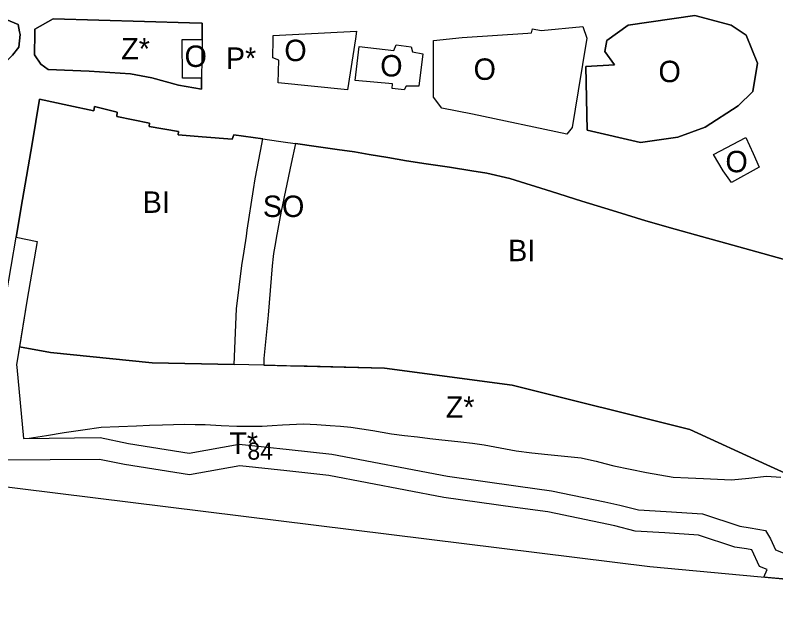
# Model space of a CAD drawing. Extents: x -521621 to -516769, y -1190068 to -1185078.
# Drawn here: x -519302 to -518947.5, y -1187581.5 to -1187307.9 of the extents above; entities that cross this region are included whole.
import ezdxf

# ---------------------------------------------------------------- set-up
doc = ezdxf.new("R2010")
doc.units = 0
for name, color, linetype in [('bydleni_s', 7, 'Continuous'), ('fpl_id', 7, 'Continuous'), ('s_zelen_s', 7, 'Continuous'), ('sm_vyuziti_s', 7, 'Continuous'), ('v_infrastr_n', 7, 'Continuous'), ('v_infrastr_s', 7, 'Continuous')]:
    doc.layers.add(name, color=color, linetype=linetype)

msp = doc.modelspace()

# ---------------------------------------------------------------- linework, layer by layer
at = {"layer": 'bydleni_s'}
for p, q in [((-519214.96, -1187364.54), (-519226.07, -1187363.63)), ((-519200.88, -1187365.69), (-519214.96, -1187364.54)), ((-519152.01, -1187370.5), (-519161.84, -1187369.1)), ((-519128.44, -1187374.31), (-519137.12, -1187372.82)), ((-519119.6, -1187375.83), (-519128.44, -1187374.31)), ((-519110.5, -1187377.14), (-519119.6, -1187375.83)), ((-519099.69, -1187378.8), (-519110.5, -1187377.14)), ((-519089.19, -1187380.42), (-519099.69, -1187378.8)), ((-519082.28, -1187381.48), (-519089.19, -1187380.42)), ((-519071.47, -1187384.11), (-519082.28, -1187381.48)), ((-519052.05, -1187390.16), (-519071.47, -1187384.11)), ((-519037.91, -1187394.56), (-519052.05, -1187390.16)), ((-519023.63, -1187399.01), (-519037.91, -1187394.56)), ((-519017.05, -1187401.06), (-519023.63, -1187399.01)), ((-519008.05, -1187403.86), (-519017.05, -1187401.06)), ((-518994.45, -1187407.64), (-519008.05, -1187403.86)), ((-518982.16, -1187411.05), (-518994.45, -1187407.64)), ((-518970.39, -1187414.32), (-518982.16, -1187411.05)), ((-518959.17, -1187417.44), (-518970.39, -1187414.32)), ((-518944.16, -1187421.61), (-518959.17, -1187417.44))]:
    msp.add_line(p, q, dxfattribs=at)
for points in [[(-519277.04, -1187349.99), (-519290.68, -1187347.06), (-519294.21, -1187367.8), (-519298.64, -1187393.79)], [(-519265.4, -1187352.49), (-519277.04, -1187349.99)], [(-519254.63, -1187355.11), (-519254.54, -1187353.15), (-519265.03, -1187350.52), (-519265.4, -1187352.49)], [(-519239.65, -1187359.79), (-519239.46, -1187358.2), (-519254.63, -1187355.11)], [(-519226.07, -1187363.63), (-519225.88, -1187362.13), (-519239.65, -1187359.79)], [(-519196.44, -1187424.58), (-519195.4, -1187417.92), (-519194.31, -1187410.93), (-519193.87, -1187408.08), (-519190.92, -1187389.18), (-519190.15, -1187384.26), (-519187.66, -1187371.24), (-519186.58, -1187365.58), (-519200.13, -1187363.65), (-519200.88, -1187365.69)], [(-519161.84, -1187369.1), (-519171.37, -1187367.75), (-519173.38, -1187377.11), (-519178.15, -1187399.27), (-519180.35, -1187411.82), (-519180.72, -1187413.92), (-519181.61, -1187418.96), (-519181.86, -1187420.41), (-519182.22, -1187424.83)], [(-519137.12, -1187372.82), (-519143.9, -1187371.66), (-519152.01, -1187370.5)], [(-519298.64, -1187393.79), (-519301.65, -1187411.41), (-519291.84, -1187413.36)], [(-519291.84, -1187413.36), (-519296.46, -1187440.4), (-519300.11, -1187462.57), (-519285.55, -1187465.16), (-519238.18, -1187469.96), (-519199.96, -1187470.86), (-519198.95, -1187444.91)], [(-519198.95, -1187444.91), (-519196.44, -1187424.58)], [(-519182.22, -1187424.83), (-519184.17, -1187447.8), (-519186.1, -1187468.02), (-519186.18, -1187471.19), (-519129.96, -1187472.52), (-519070.49, -1187480.41), (-518987.59, -1187501.17), (-518951.77, -1187517.59)], [(-518951.77, -1187517.59), (-518938.37, -1187523.73), (-518937.12, -1187522.83)]]:
    msp.add_lwpolyline(points, dxfattribs=at)
at = {"layer": 's_zelen_s'}
for points in [[(-519340.83, -1187326.07), (-519308.14, -1187331.14), (-519303.3, -1187326.48), (-519300.34, -1187322.71), (-519299.8, -1187316.88), (-519300.01, -1187315.67), (-519300.61, -1187312.13), (-519306.33, -1187309.9), (-519322.8, -1187308.87), (-519367.14, -1187306.08), (-519395.14, -1187302.99), (-519449.32, -1187297), (-519480.57, -1187293.55), (-519511.5, -1187291.57), (-519525.87, -1187288.75), (-519526.08, -1187289.83), (-519527.1, -1187295.05), (-519498.34, -1187299.98), (-519398.99, -1187315.96), (-519340.83, -1187326.07)], [(-519224.22, -1187319.17), (-519214.96, -1187319.25), (-519214.91, -1187311.57), (-519220.85, -1187311.4), (-519241.74, -1187310.81), (-519284.42, -1187309.62), (-519292.9, -1187314.37), (-519292.91, -1187316.03), (-519292.99, -1187326.39), (-519290.12, -1187330.7), (-519286.71, -1187333.21), (-519267.61, -1187334.02), (-519248.26, -1187335.27), (-519238.31, -1187337.06), (-519225.93, -1187340.47), (-519215.19, -1187342.31), (-519215.19, -1187337.23), (-519224.06, -1187337.31), (-519224.22, -1187319.17)], [(-519300.11, -1187462.57), (-519301.49, -1187470.89), (-519301.23, -1187472.1), (-519298.18, -1187505.33), (-519295.55, -1187505.13)], [(-519199.96, -1187470.86), (-519238.18, -1187469.96), (-519285.55, -1187465.16), (-519300.11, -1187462.57)], [(-519186.18, -1187471.19), (-519193.2, -1187471.02), (-519199.96, -1187470.86)], [(-519175.55, -1187471.44), (-519186.18, -1187471.19)], [(-519166.03, -1187471.66), (-519175.55, -1187471.44)], [(-518951.77, -1187517.59), (-518987.59, -1187501.17), (-519070.49, -1187480.41), (-519129.96, -1187472.52), (-519166.03, -1187471.66)], [(-519295.55, -1187505.13), (-519287.41, -1187503.86), (-519279.26, -1187502.6), (-519270.6, -1187501.33), (-519261.94, -1187500.07), (-519253.7, -1187499.74), (-519245.46, -1187499.41), (-519239.43, -1187499.15), (-519233.4, -1187498.89), (-519228.23, -1187498.74), (-519223.06, -1187498.58), (-519218.24, -1187498.72), (-519213.43, -1187498.85), (-519206.12, -1187499.23), (-519198.82, -1187499.6), (-519192.88, -1187499.55), (-519186.93, -1187499.51), (-519182.2, -1187499.2), (-519177.46, -1187498.89)], [(-519177.46, -1187498.89), (-519167.66, -1187498.42)], [(-519167.66, -1187498.42), (-519161.42, -1187498.86), (-519155.19, -1187499.3), (-519150.43, -1187499.64), (-519145.67, -1187499.97), (-519140.5, -1187500.81), (-519135.33, -1187501.66), (-519131.01, -1187502.4), (-519126.68, -1187503.13), (-519120.62, -1187503.86), (-519114.57, -1187504.6), (-519108.86, -1187505.29), (-519103.15, -1187505.98), (-519098.75, -1187506.41), (-519094.35, -1187506.83), (-519088.91, -1187507.56), (-519083.47, -1187508.3), (-519076.03, -1187509.73), (-519068.58, -1187511.15), (-519061.21, -1187512), (-519053.84, -1187512.85), (-519046.09, -1187513.58), (-519038.33, -1187514.32), (-519034.82, -1187515.09), (-519031.31, -1187515.86), (-519027.18, -1187516.98), (-519023.06, -1187518.1), (-519015.46, -1187519.68), (-519007.85, -1187521.26), (-519001.6, -1187522.34), (-518995.35, -1187523.42), (-518988.33, -1187523.69), (-518981.31, -1187523.96), (-518974.75, -1187524.31), (-518968.19, -1187524.66), (-518960.05, -1187523.81), (-518951.91, -1187522.96), (-518945.14, -1187523.34)], [(-518938.37, -1187523.73), (-518951.77, -1187517.59)]]:
    msp.add_lwpolyline(points, dxfattribs=at)
at = {"layer": 'sm_vyuziti_s'}
for points in [[(-519196.44, -1187424.58), (-519195.4, -1187417.92), (-519194.31, -1187410.93), (-519193.87, -1187408.08), (-519190.92, -1187389.18), (-519190.15, -1187384.26), (-519187.66, -1187371.24), (-519186.58, -1187365.58), (-519179.4, -1187366.6), (-519174.98, -1187367.23), (-519171.37, -1187367.75), (-519173.38, -1187377.11), (-519178.15, -1187399.27), (-519180.35, -1187411.82), (-519180.72, -1187413.92), (-519181.61, -1187418.96), (-519181.86, -1187420.41), (-519182.22, -1187424.83)], [(-519186.18, -1187471.19), (-519193.2, -1187471.02), (-519199.96, -1187470.86), (-519198.95, -1187444.91), (-519196.44, -1187424.58)], [(-519182.22, -1187424.83), (-519184.17, -1187447.8), (-519186.1, -1187468.02), (-519186.18, -1187471.19)]]:
    msp.add_lwpolyline(points, dxfattribs=at)
at = {"layer": 'v_infrastr_n'}
for points in [[(-519306.32, -1187438.74), (-519301.65, -1187411.41), (-519291.84, -1187413.36), (-519296.46, -1187440.4), (-519301.49, -1187470.89), (-519301.23, -1187472.1), (-519298.18, -1187505.33), (-519262.49, -1187504.9), (-519249.3, -1187507.6), (-519220.9, -1187512.16), (-519197.67, -1187507.99), (-519174.37, -1187510.46), (-519154.46, -1187512.62), (-519100.6, -1187522.96), (-519067.64, -1187527.61), (-519052.16, -1187529.73), (-519027.25, -1187534.85), (-519020.25, -1187536.36), (-519011.55, -1187538.56), (-518998.58, -1187539.34), (-518981.68, -1187540.49), (-518964.24, -1187546.2), (-518959.53, -1187546.94), (-518952.28, -1187548.29), (-518950.02, -1187552.18), (-518947.74, -1187557.27), (-518938.14, -1187561)], [(-519790.94, -1187475.66), (-519421.47, -1187513.5), (-519006.29, -1187565.08), (-518941.03, -1187571.03), (-518921.54, -1187583.59)], [(-518941.03, -1187571.03), (-518953.05, -1187569.94), (-518951.61, -1187566.49), (-518955.19, -1187565.1), (-518958.7, -1187557.27), (-518961.22, -1187556.8), (-518966.59, -1187555.95), (-518983.6, -1187550.38), (-518999.22, -1187549.32), (-519013.09, -1187548.49), (-519022.53, -1187546.1), (-519029.31, -1187544.64), (-519053.85, -1187539.59), (-519069.02, -1187537.51), (-519102.24, -1187532.83), (-519155.94, -1187522.52), (-519175.44, -1187520.4), (-519197.31, -1187518.08), (-519220.81, -1187522.3), (-519251.1, -1187517.44), (-519262.71, -1187515.06), (-519308.73, -1187515.41)]]:
    msp.add_lwpolyline(points, dxfattribs=at)
at = {"layer": 'v_infrastr_s'}
msp.add_line((-519119.6, -1187375.83), (-519110.5, -1187377.14), dxfattribs=at)
for points in [[(-519340.83, -1187326.07), (-519398.99, -1187315.96), (-519498.34, -1187299.98), (-519527.1, -1187295.05), (-519526.08, -1187289.83), (-519525.87, -1187288.75), (-519511.5, -1187291.57), (-519480.57, -1187293.55), (-519449.32, -1187297), (-519395.14, -1187302.99), (-519367.14, -1187306.08), (-519322.8, -1187308.87), (-519306.33, -1187309.9), (-519300.61, -1187312.13), (-519300.01, -1187315.67), (-519299.8, -1187316.88), (-519300.34, -1187322.71), (-519303.3, -1187326.48), (-519308.14, -1187331.14), (-519340.83, -1187326.07)], [(-519215.19, -1187337.23), (-519215.19, -1187342.31), (-519225.93, -1187340.47), (-519238.31, -1187337.06), (-519248.26, -1187335.27), (-519267.61, -1187334.02), (-519286.71, -1187333.21), (-519290.12, -1187330.7), (-519292.99, -1187326.39), (-519292.91, -1187316.03), (-519292.9, -1187314.37), (-519284.42, -1187309.62), (-519241.74, -1187310.81), (-519220.85, -1187311.4), (-519214.91, -1187311.57), (-519214.96, -1187319.25)], [(-518958.2, -1187343.4), (-518956, -1187330.25), (-518961.33, -1187317.13), (-518968.31, -1187312.54), (-518985.28, -1187308.06), (-519016.3, -1187312.54), (-519026.33, -1187319.64), (-519027.26, -1187324.73), (-519022.79, -1187331.06), (-519036.06, -1187331.83), (-519035.44, -1187361.46), (-519010.67, -1187367.17), (-518993.16, -1187364.78), (-518980.5, -1187360.15), (-518965.07, -1187350.12), (-518958.2, -1187343.4)], [(-519010.67, -1187367.17), (-519035.44, -1187361.46), (-519036.06, -1187331.83), (-519022.79, -1187331.06), (-519027.26, -1187324.73), (-519026.33, -1187319.64), (-519016.3, -1187312.54), (-518985.28, -1187308.06), (-518968.31, -1187312.54), (-518961.33, -1187317.13), (-518956, -1187330.25), (-518958.2, -1187343.4)], [(-519107.09, -1187319.64), (-519093.74, -1187318.21), (-519063.09, -1187316.17), (-519061.33, -1187316.05), (-519060.94, -1187314.2), (-519056.93, -1187315.05), (-519037.41, -1187313.19), (-519035.63, -1187318.52), (-519039.68, -1187343.1), (-519042.5, -1187360.19), (-519045.01, -1187363.39)], [(-519056.93, -1187315.05), (-519037.41, -1187313.19), (-519035.63, -1187318.52), (-519039.68, -1187343.1)], [(-519181.85, -1187319.02), (-519181.82, -1187317.28), (-519142.93, -1187315.35), (-519143.47, -1187318.86)], [(-519093.74, -1187318.21), (-519063.09, -1187316.17), (-519061.33, -1187316.05), (-519060.94, -1187314.2), (-519056.93, -1187315.05)], [(-519214.96, -1187319.25), (-519215.19, -1187337.23)], [(-519143.47, -1187318.86), (-519147.15, -1187342.73), (-519179.48, -1187339.49), (-519179.19, -1187328.78), (-519181.97, -1187327.7), (-519181.85, -1187319.02)], [(-519039.68, -1187343.1), (-519042.5, -1187360.19), (-519045.01, -1187363.39), (-519088.84, -1187353.97), (-519103.23, -1187351.22), (-519107.09, -1187346.03), (-519107.09, -1187319.64), (-519093.74, -1187318.21)], [(-519103.23, -1187351.22), (-519107.09, -1187346.03), (-519107.09, -1187319.64)], [(-519143.66, -1187338.31), (-519141.65, -1187322.49)], [(-519141.65, -1187322.49), (-519125.6, -1187324.27), (-519124.45, -1187321.72), (-519117.5, -1187322.65), (-519116.88, -1187324.96), (-519112.1, -1187325.81)], [(-519112.1, -1187325.81), (-519113.95, -1187341.01)], [(-519113.95, -1187341.01), (-519119.89, -1187340.93), (-519120.74, -1187342.63), (-519126.38, -1187342.01), (-519126.14, -1187339.85), (-519143.66, -1187338.31)], [(-518958.2, -1187343.4), (-518965.07, -1187350.12)], [(-519301.65, -1187411.41), (-519298.64, -1187393.79), (-519294.21, -1187367.8), (-519290.68, -1187347.06), (-519277.04, -1187349.99), (-519265.4, -1187352.49), (-519265.03, -1187350.52), (-519254.54, -1187353.15), (-519254.63, -1187355.11), (-519239.46, -1187358.2), (-519239.65, -1187359.79), (-519225.88, -1187362.13), (-519226.07, -1187363.63), (-519214.96, -1187364.54), (-519200.88, -1187365.69), (-519200.13, -1187363.65), (-519186.58, -1187365.58), (-519179.4, -1187366.6), (-519174.98, -1187367.23), (-519174.98, -1187367.23), (-519171.37, -1187367.75), (-519161.84, -1187369.1), (-519152.01, -1187370.5), (-519143.9, -1187371.66), (-519137.12, -1187372.82), (-519128.44, -1187374.31), (-519119.6, -1187375.83)], [(-519088.84, -1187353.97), (-519103.23, -1187351.22)], [(-518965.07, -1187350.12), (-518980.5, -1187360.15)], [(-519045.01, -1187363.39), (-519088.84, -1187353.97)], [(-518980.5, -1187360.15), (-518993.16, -1187364.78)], [(-518993.16, -1187364.78), (-519010.67, -1187367.17)], [(-519110.5, -1187377.14), (-519099.69, -1187378.8), (-519089.19, -1187380.42), (-519082.28, -1187381.48), (-519071.47, -1187384.11), (-519052.05, -1187390.16), (-519037.91, -1187394.56), (-519023.63, -1187399.01), (-519017.05, -1187401.06), (-519008.05, -1187403.86), (-518994.45, -1187407.64), (-518982.16, -1187411.05), (-518970.39, -1187414.32), (-518959.17, -1187417.44), (-518944.16, -1187421.61), (-518932.74, -1187427.78)], [(-519311.66, -1187471.13), (-519306.32, -1187438.74), (-519301.65, -1187411.41)]]:
    msp.add_lwpolyline(points, dxfattribs=at)
for points in [[(-519181.97, -1187327.7), (-519181.85, -1187319.02), (-519181.82, -1187317.28), (-519142.93, -1187315.35), (-519143.47, -1187318.86), (-519147.15, -1187342.73), (-519179.48, -1187339.49), (-519179.19, -1187328.78)], [(-519224.22, -1187319.17), (-519214.96, -1187319.25), (-519215.19, -1187337.23), (-519224.06, -1187337.31)], [(-519143.66, -1187338.31), (-519141.65, -1187322.49), (-519125.6, -1187324.27), (-519124.45, -1187321.72), (-519117.5, -1187322.65), (-519116.88, -1187324.96), (-519112.1, -1187325.81), (-519113.95, -1187341.01), (-519119.89, -1187340.93), (-519120.74, -1187342.63), (-519126.38, -1187342.01), (-519126.14, -1187339.85)], [(-518976.57, -1187372.92), (-518961.44, -1187364.89), (-518958.07, -1187372.43), (-518955.27, -1187378.7), (-518968.15, -1187385.96), (-518972.09, -1187380.4)], [(-518976.57, -1187372.92), (-518961.44, -1187364.89), (-518958.07, -1187372.43), (-518955.27, -1187378.7), (-518968.15, -1187385.96), (-518972.09, -1187380.4)]]:
    msp.add_lwpolyline(points, close=True, dxfattribs=at)

# ---------------------------------------------------------------- texts
at = {"layer": 'bydleni_s'}
for p in [(-519242.6, -1187400.06), (-519072.29, -1187422.61)]:
    msp.add_text('BI', height=10, dxfattribs=at).set_placement(p)
at = {"layer": 'fpl_id'}
msp.add_text('84', height=8, dxfattribs=at).set_placement((-519193.81, -1187515.2))
at = {"layer": 's_zelen_s'}
for p in [(-519252.63, -1187328.5), (-519101.34, -1187495.67)]:
    msp.add_text('Z*', height=10, dxfattribs=at).set_placement(p)
at = {"layer": 'sm_vyuziti_s'}
msp.add_text('SO', height=10, dxfattribs=at).set_placement((-519186.61, -1187402.01))
at = {"layer": 'v_infrastr_n'}
msp.add_text('T*', height=10, dxfattribs=at).set_placement((-519202.22, -1187512.5))
at = {"layer": 'v_infrastr_s'}
for s, p in [('O', (-519176.6, -1187329.28)), ('O', (-519223.1, -1187332)), ('P*', (-519203.84, -1187332.91)), ('O', (-519131.89, -1187336.45)), ('O', (-519088.39, -1187338.03)), ('O', (-519002.22, -1187339.11)), ('O', (-518971.01, -1187381.13))]:
    msp.add_text(s, height=10, dxfattribs=at).set_placement(p)

doc.saveas('drawing.dxf')
